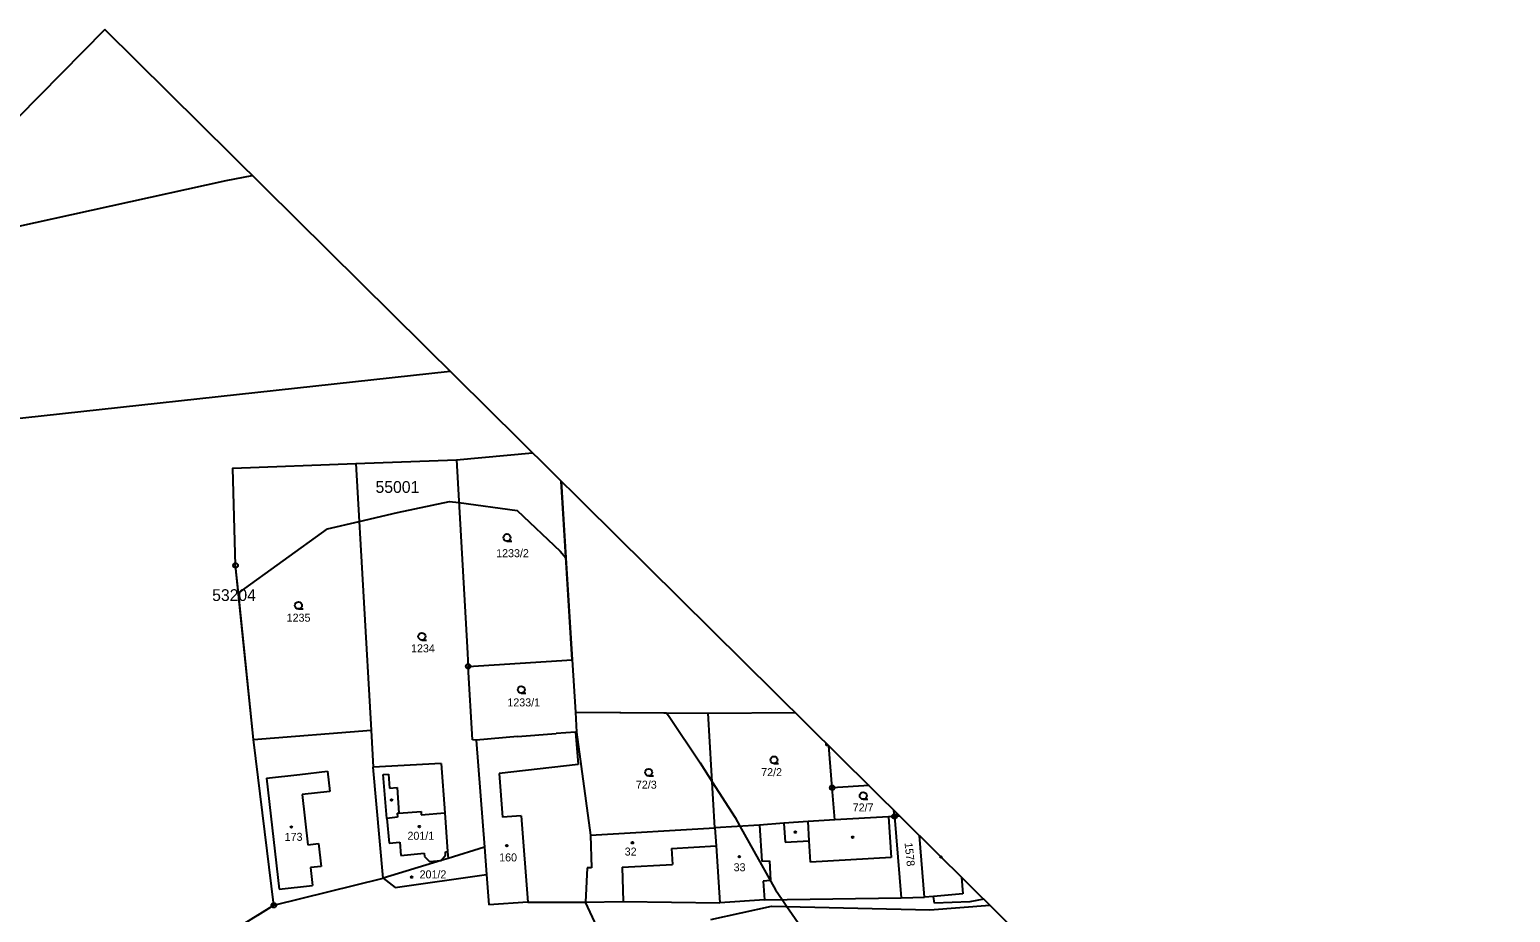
# Model space of a CAD drawing. Extents: x -777175 to -776673, y -1110537 to -1110036.
# Drawn here: x -776987.6 to -776672.9, y -1110223.9 to -1110036.4 of the extents above; entities that cross this region are included whole.
import ezdxf

# ---------------------------------------------------------------- set-up
doc = ezdxf.new("R2010")
doc.units = 0
for name, color, linetype in [('BPEJ', 7, 'Continuous'), ('Katastr_Hranice parcel', 7, 'Continuous'), ('Katastr_Parcelní čísla', 7, 'Continuous'), ('Katastr_Slučkované čáry', 7, 'Continuous'), ('Katastr_Značky kultur', 7, 'Continuous')]:
    doc.layers.add(name, color=color, linetype=linetype)

msp = doc.modelspace()

# ---------------------------------------------------------------- linework, layer by layer
at = {"layer": 'BPEJ'}
for points in [[(-776943.23, -1110156.15), (-776943.84, -1110150.23), (-776944.43, -1110129.54), (-776918.27, -1110128.61), (-776896.87, -1110127.82), (-776880.71, -1110126.3)], [(-776874.64, -1110132.31), (-776873.64, -1110148.61)], [(-776943.16, -1110156.08), (-776924.3, -1110142.48), (-776917.57, -1110140.89), (-776909.43, -1110138.96), (-776898.38, -1110136.63), (-776896.36, -1110136.9), (-776884.02, -1110138.59), (-776874.85, -1110147.22), (-776873.64, -1110148.61)], [(-776873.64, -1110148.61), (-776872.31, -1110170.3), (-776871.63, -1110181.37), (-776852.23, -1110181.54)], [(-776943.23, -1110156.15), (-776943.16, -1110156.08)], [(-776943.1, -1110157.36), (-776943.23, -1110156.15)], [(-776943.1, -1110157.36), (-776943.16, -1110156.08)], [(-776939.07, -1110224.48), (-776935.71, -1110222.4), (-776940, -1110187.19), (-776943.1, -1110157.36)], [(-776852.23, -1110181.54), (-776843.41, -1110181.62), (-776824.95, -1110181.44)], [(-776852.23, -1110181.54), (-776851.73, -1110182.33), (-776845.13, -1110192.18), (-776842.54, -1110196.21), (-776837.7, -1110203.74), (-776836.65, -1110205.62), (-776829.07, -1110219.13), (-776827.66, -1110221.2), (-776826.66, -1110222.65), (-776822.05, -1110229.41), (-776821.58, -1110229.97), (-776818.14, -1110234.08), (-776814.62, -1110238.29), (-776805.87, -1110248.74), (-776802.05, -1110253.25), (-776793.36, -1110263.5)]]:
    msp.add_lwpolyline(points, dxfattribs=at)
at = {"layer": 'Defpoints'}
for p, q in [((-776971.6, -1110036.44), (-777174.79, -1110241.95)), ((-776672.94, -1110331.74), (-776971.6, -1110036.44))]:
    msp.add_line(p, q, dxfattribs=at)
at = {"layer": 'Katastr_Hranice parcel'}
for points in [[(-777019.23, -1110084.62), (-776945.83, -1110068.47), (-776940.28, -1110067.41)], [(-777071.41, -1110137.39), (-777071.39, -1110137.43), (-777016.29, -1110136.81), (-777017.63, -1110122), (-776898.22, -1110109)], [(-776896.87, -1110127.82), (-776880.71, -1110126.3)], [(-776944.43, -1110129.54), (-776918.27, -1110128.61)], [(-776943.84, -1110150.23), (-776944.43, -1110129.54)], [(-776918.27, -1110128.61), (-776896.87, -1110127.82)], [(-776918.27, -1110128.61), (-776915.03, -1110185.23)], [(-776896.87, -1110127.82), (-776894.63, -1110167.56)], [(-776872.31, -1110170.3), (-776874.64, -1110132.31)], [(-776940, -1110187.19), (-776943.84, -1110150.23)], [(-776894.63, -1110167.56), (-776894.4, -1110171.66)], [(-776894.4, -1110171.66), (-776872.31, -1110170.3)], [(-776872.31, -1110170.3), (-776871.63, -1110181.37)], [(-776893.49, -1110187.3), (-776894.4, -1110171.66)], [(-776871.63, -1110181.37), (-776843.41, -1110181.62)], [(-776871.63, -1110181.37), (-776871.37, -1110185.65)], [(-776843.41, -1110181.62), (-776824.95, -1110181.44)], [(-776841.96, -1110205.94), (-776843.41, -1110181.62)], [(-776940, -1110187.19), (-776915.03, -1110185.23)], [(-776915.03, -1110185.23), (-776914.58, -1110193.06)], [(-776883.94, -1110186.59), (-776892.68, -1110187.37)], [(-776883.94, -1110186.59), (-776875.69, -1110185.94)], [(-776871.62, -1110185.62), (-776875.69, -1110185.94)], [(-776871.37, -1110185.65), (-776871.62, -1110185.62)], [(-776871.37, -1110185.65), (-776868.38, -1110207.5)], [(-776935.71, -1110222.4), (-776940, -1110187.19)], [(-776892.68, -1110187.37), (-776893.49, -1110187.3)], [(-776892.68, -1110187.37), (-776890.97, -1110210.05)], [(-776818.33, -1110188.48), (-776818.33, -1110187.99)], [(-776817.83, -1110188.48), (-776818.33, -1110188.48)], [(-776817.04, -1110197.43), (-776817.78, -1110188.54)], [(-776900.12, -1110192.28), (-776914.58, -1110193.06)], [(-776900.12, -1110192.28), (-776899.38, -1110202.78)], [(-776912.44, -1110216.65), (-776914.58, -1110193.06)], [(-776809.21, -1110197), (-776817.04, -1110197.43)], [(-776816.48, -1110204.27), (-776817.04, -1110197.43)], [(-776803.82, -1110203.55), (-776803.93, -1110202.23)], [(-776899.38, -1110202.78), (-776898.8, -1110210.98)], [(-776832.52, -1110205.37), (-776841.96, -1110205.94)], [(-776827.3, -1110204.95), (-776832.52, -1110205.37)], [(-776822.18, -1110204.58), (-776827.3, -1110204.95)], [(-776816.48, -1110204.27), (-776822.18, -1110204.58)], [(-776805.07, -1110203.65), (-776816.48, -1110204.27)], [(-776803.82, -1110203.55), (-776805.07, -1110203.65)], [(-776802.69, -1110203.45), (-776803.82, -1110203.55)], [(-776803.82, -1110203.55), (-776802.41, -1110220.8)], [(-776868.38, -1110207.5), (-776841.96, -1110205.94)], [(-776868.38, -1110207.5), (-776868.19, -1110214.46)], [(-776841.96, -1110205.94), (-776841.72, -1110209.81)], [(-776797.41, -1110220.68), (-776798.47, -1110207.62)], [(-776898.8, -1110210.98), (-776898.69, -1110212.47)], [(-776890.97, -1110210.05), (-776898.69, -1110212.47)], [(-776890.97, -1110210.05), (-776890.52, -1110215.9)], [(-776841.72, -1110209.81), (-776840.96, -1110221.85)], [(-776900.13, -1110212.92), (-776912.44, -1110216.65)], [(-776898.69, -1110212.47), (-776900.13, -1110212.92)], [(-776869.09, -1110214.44), (-776869.45, -1110221.75)], [(-776868.19, -1110214.46), (-776869.09, -1110214.44)], [(-776935.71, -1110222.4), (-776912.44, -1110216.65)], [(-776912.44, -1110216.65), (-776909.94, -1110218.64)], [(-776909.94, -1110218.64), (-776890.52, -1110215.9)], [(-776890.52, -1110215.9), (-776890.04, -1110222.28)], [(-776831.47, -1110221.26), (-776802.41, -1110220.8)], [(-776802.41, -1110220.8), (-776797.41, -1110220.68)], [(-776795.55, -1110220.51), (-776797.41, -1110220.68)], [(-776795.28, -1110221.95), (-776795.55, -1110220.51)], [(-776784.84, -1110221.11), (-776787.79, -1110221.67)], [(-776951.61, -1110232.24), (-776935.71, -1110222.4)], [(-776881.76, -1110221.77), (-776890.04, -1110222.28)], [(-776881.76, -1110221.77), (-776869.45, -1110221.75)], [(-776869.45, -1110221.75), (-776861.46, -1110221.61)], [(-776862.67, -1110236.36), (-776869.45, -1110221.75)], [(-776861.46, -1110221.61), (-776840.96, -1110221.85)], [(-776842.87, -1110225.4), (-776829.97, -1110222.58)], [(-776831.47, -1110221.26), (-776840.96, -1110221.85)], [(-776829.97, -1110222.58), (-776796.3, -1110223.34)], [(-776796.3, -1110223.34), (-776783.54, -1110222.38)], [(-776787.79, -1110221.67), (-776795.28, -1110221.95)]]:
    msp.add_lwpolyline(points, dxfattribs=at)
at = {"layer": 'Katastr_Slučkované čáry'}
for points in [[(-776871.62, -1110185.62), (-776871.05, -1110192.53)], [(-776871.05, -1110192.53), (-776887.84, -1110194.44)], [(-776937.25, -1110195.4), (-776930.17, -1110194.6)], [(-776937.25, -1110195.4), (-776934.6, -1110218.95)], [(-776930.17, -1110194.6), (-776924.28, -1110193.94)], [(-776924.28, -1110193.94), (-776923.79, -1110198.23)], [(-776912.45, -1110194.65), (-776911.33, -1110194.55)], [(-776911.72, -1110203.95), (-776912.45, -1110194.65)], [(-776911.33, -1110194.55), (-776911.1, -1110197.54)], [(-776887.84, -1110194.44), (-776887.14, -1110203.67)], [(-776923.79, -1110198.23), (-776929.68, -1110198.89)], [(-776929.68, -1110198.89), (-776928.49, -1110209.54)], [(-776911.1, -1110197.54), (-776909.52, -1110197.39)], [(-776909.52, -1110197.39), (-776909.11, -1110202.82)], [(-776909.41, -1110203.69), (-776911.72, -1110203.95)], [(-776911.72, -1110203.95), (-776911.21, -1110209.2)], [(-776909.49, -1110202.85), (-776909.11, -1110202.82)], [(-776909.49, -1110202.85), (-776909.41, -1110203.69)], [(-776909.11, -1110202.82), (-776904.42, -1110202.51)], [(-776904.42, -1110202.51), (-776904.37, -1110203.17)], [(-776904.37, -1110203.17), (-776899.38, -1110202.78)], [(-776883.15, -1110203.42), (-776887.14, -1110203.67)], [(-776883.15, -1110203.42), (-776881.76, -1110221.77)], [(-776832.52, -1110205.37), (-776832.01, -1110213.07)], [(-776827.3, -1110204.95), (-776827.04, -1110209.02)], [(-776821.94, -1110208.7), (-776822.18, -1110204.58)], [(-776805.07, -1110203.65), (-776804.52, -1110212.23)], [(-776928.49, -1110209.54), (-776926.2, -1110209.29)], [(-776926.2, -1110209.29), (-776925.66, -1110214.16)], [(-776911.21, -1110209.2), (-776908.93, -1110208.99)], [(-776908.93, -1110208.99), (-776908.69, -1110211.82)], [(-776908.69, -1110211.82), (-776903.74, -1110211.37)], [(-776903.74, -1110211.37), (-776903.69, -1110212.07)], [(-776899.26, -1110211.03), (-776898.8, -1110210.98)], [(-776899.2, -1110211.79), (-776899.26, -1110211.03)], [(-776851.17, -1110210.37), (-776841.72, -1110209.81)], [(-776851.17, -1110210.37), (-776850.96, -1110213.71)], [(-776827.04, -1110209.02), (-776821.94, -1110208.7)], [(-776821.67, -1110213.27), (-776821.94, -1110208.7)], [(-776925.66, -1110214.16), (-776927.94, -1110214.41)], [(-776927.94, -1110214.41), (-776927.52, -1110218.19)], [(-776903.69, -1110212.07), (-776902.6, -1110213.11)], [(-776902.6, -1110213.11), (-776900.13, -1110212.92)], [(-776900.13, -1110212.92), (-776899.2, -1110211.79)], [(-776861.66, -1110214.34), (-776850.96, -1110213.71)], [(-776861.66, -1110214.34), (-776861.46, -1110221.61)], [(-776832.01, -1110213.07), (-776830.41, -1110212.96)], [(-776830.41, -1110212.96), (-776830.14, -1110217.16)], [(-776804.52, -1110212.23), (-776821.67, -1110213.27)], [(-776830.14, -1110217.16), (-776831.73, -1110217.26)], [(-776831.73, -1110217.26), (-776831.47, -1110221.26)], [(-776789.56, -1110216.44), (-776789.26, -1110219.94)], [(-776934.6, -1110218.95), (-776927.52, -1110218.19)], [(-776789.26, -1110219.94), (-776795.55, -1110220.51)]]:
    msp.add_lwpolyline(points, dxfattribs=at)
at = {"layer": 'Katastr_Značky kultur'}
for p, q in [((-776886.16, -1110145.05), (-776885.16, -1110145.05)), ((-776943.89, -1110150.23), (-776943.79, -1110150.23)), ((-776930.48, -1110159.48), (-776929.48, -1110159.48)), ((-776904.25, -1110166.07), (-776903.25, -1110166.07)), ((-776894.45, -1110171.66), (-776894.35, -1110171.66)), ((-776883.12, -1110177.38), (-776882.12, -1110177.38)), ((-776829.43, -1110192.28), (-776828.43, -1110192.28)), ((-776856.05, -1110194.94), (-776855.05, -1110194.94)), ((-776817.09, -1110197.43), (-776816.99, -1110197.43)), ((-776810.46, -1110199.9), (-776809.46, -1110199.9)), ((-776803.87, -1110203.55), (-776803.77, -1110203.55)), ((-776935.76, -1110222.4), (-776935.66, -1110222.4))]:
    msp.add_line(p, q, dxfattribs=at)
for centre, radius in [((-776886.16, -1110144.3), 0.75), ((-776943.84, -1110150.23), 0.499), ((-776930.48, -1110158.73), 0.75), ((-776904.25, -1110165.32), 0.75), ((-776894.4, -1110171.66), 0.499), ((-776883.12, -1110176.63), 0.75), ((-776829.43, -1110191.53), 0.75), ((-776856.05, -1110194.19), 0.75), ((-776817.04, -1110197.43), 0.499), ((-776810.46, -1110199.15), 0.75), ((-776910.69, -1110200.05), 0.175), ((-776803.82, -1110203.55), 0.499), ((-776931.98, -1110205.79), 0.175), ((-776904.78, -1110205.68), 0.175), ((-776824.89, -1110206.87), 0.175), ((-776812.7, -1110207.95), 0.175), ((-776886.2, -1110209.76), 0.175), ((-776859.5, -1110209.14), 0.175), ((-776836.79, -1110212.08), 0.175), ((-776793.92, -1110212.14), 0.175), ((-776906.42, -1110216.42), 0.175), ((-776935.71, -1110222.4), 0.499)]:
    msp.add_circle(centre, radius, dxfattribs=at)

# ---------------------------------------------------------------- texts
at = {"layer": 'BPEJ'}
for s, p in [('55001', (-776914.09, -1110134.82)), ('53204', (-776948.81, -1110157.78))]:
    msp.add_text(s, height=2.5, dxfattribs=at).set_placement(p)
at = {"layer": 'Katastr_Parcelní čísla'}
for s, p in [('1233/2', (-776888.46, -1110148.48)), ('1235', (-776932.98, -1110162.18)), ('1234', (-776906.55, -1110168.69)), ('1233/1', (-776886.08, -1110180.17)), ('72/3', (-776858.76, -1110197.64)), ('72/2', (-776832.14, -1110194.98)), ('72/7', (-776812.7, -1110202.48)), ('173', (-776933.4, -1110208.72)), ('201/1', (-776907.31, -1110208.49)), ('160', (-776887.82, -1110213.09)), ('32', (-776861.15, -1110211.85)), ('201/2', (-776904.73, -1110216.69)), ('33', (-776838, -1110215.18))]:
    msp.add_text(s, height=1.7, dxfattribs=at).set_placement(p)
msp.add_text('1578', height=1.7, rotation=275.8361, dxfattribs=at).set_placement((-776801.68, -1110209.17))

doc.saveas('drawing.dxf')
